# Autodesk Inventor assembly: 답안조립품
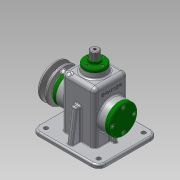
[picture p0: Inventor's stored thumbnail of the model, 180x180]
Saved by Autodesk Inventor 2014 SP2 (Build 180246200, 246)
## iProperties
Created: 2016-08
Part Number: 답안조립품
Document SubType Name: Assembly
Designer: user
Author: user
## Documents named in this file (19)
- C:\Users\user\Desktop\460820V1015\답안조립품.iam
- C:\Users\user\Desktop\460820V1015\본체.ipt
- C:\Users\user\Desktop\460820V1015\뒤커버.ipt
- C:\Users\user\Desktop\460820V1015\앞커버.ipt
- C:\Users\user\Desktop\460820V1015\베어링 15 x 35 x 11.ipt
- C:\Users\user\Desktop\460820V1015\상부부시.ipt
- C:\Users\user\Desktop\460820V1015\멈춤링 15 x 1.ipt
- C:\Users\user\Desktop\460820V1015\편심축.ipt
- C:\Users\user\Desktop\460820V1015\링크.ipt
- C:\Users\user\Desktop\460820V1015\슬라이드바.ipt
- C:\Users\user\Desktop\460820V1015\고정핀.ipt
- C:\Users\user\Desktop\460820V1015\멈춤링 6 x 5.ipt
- C:\Users\user\Desktop\460820V1015\키 5 x 5 x 14.ipt
- C:\Users\user\Desktop\460820V1015\V-벨트풀리.ipt
- C:\Users\user\Desktop\460820V1015\오일실 15 25 7.ipt
- C:\Users\user\Desktop\460820V1015\와셔.ipt
- C:\Users\user\Desktop\460820V1015\볼트 M6 x 12.ipt
- C:\Users\user\Desktop\460820V1015\볼트 M4 x 10.ipt
- C:\Users\user\Desktop\460820V1015\볼트 M3 x 8.ipt
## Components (15 placed, 5 different names)
1. 고정핀:1 — 강체:3, 강체:4, 강체:5
2. V-벨트풀리:1 — 각도:1
3. ISO 4018 M6 x 12:1 — 강체:7
4. ISO 4762 M4 x 10:2 — 강체:8
5. ISO 4762 M4 x 10:3
6. ISO 4762 M4 x 10:4
7. ISO 4762 M4 x 10:5
8. ISO 4762 M4 x 10:1 — 강체:9
9. ISO 4762 M4 x 10:6
10. ISO 4762 M4 x 10:7
11. ISO 4762 M4 x 10:8
12. ISO 4762 M3 x 8:1 — 강체:10
13. ISO 4762 M3 x 8:2
14. ISO 4762 M3 x 8:3
15. ISO 4762 M3 x 8:4
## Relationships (8: WeldJoint 7, Angle 1)
- 강체:3 [WeldJoint]: 고정핀:1
- 강체:4 [WeldJoint]: 고정핀:1
- 강체:5 [WeldJoint]: 고정핀:1
- 각도:1 [Angle]: V-벨트풀리:1
- 강체:7 [WeldJoint]: ISO 4018 M6 x 12:1
- 강체:8 [WeldJoint]: ISO 4762 M4 x 10:2
- 강체:9 [WeldJoint]: ISO 4762 M4 x 10:1
- 강체:10 [WeldJoint]: ISO 4762 M3 x 8:1
